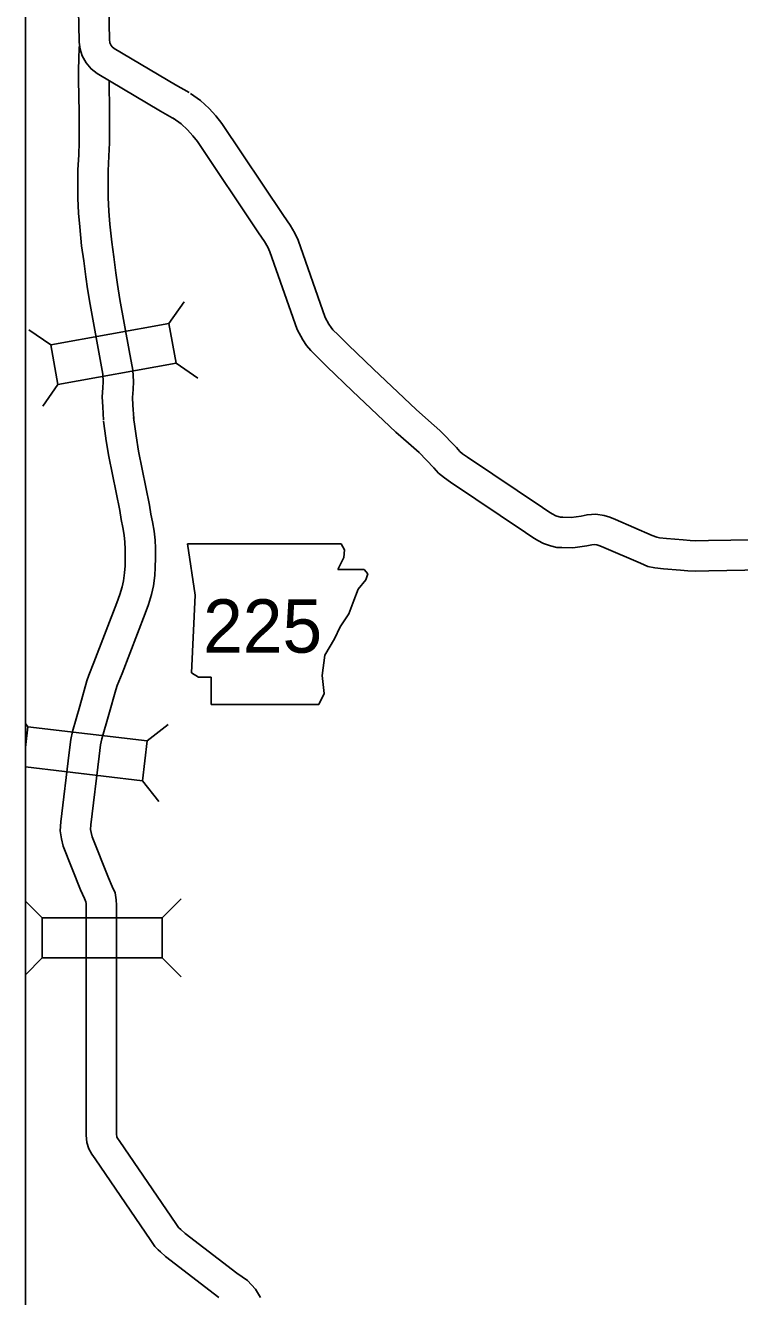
# Model space of a CAD drawing. Extents: x 1212896 to 1368412, y 378476 to 478763.
# Drawn here: x 1215273 to 1222342, y 456675 to 469257 of the extents above; entities that cross this region are included whole.
import ezdxf

# ---------------------------------------------------------------- set-up
doc = ezdxf.new("R2010")
doc.units = 0
for name, color, linetype in [('1', 7, 'Continuous'), ('Level 10', 7, 'Continuous'), ('Level 20', 7, 'Continuous'), ('Level 21', 7, 'Continuous')]:
    doc.layers.add(name, color=color, linetype=linetype)

msp = doc.modelspace()

# ---------------------------------------------------------------- linework, layer by layer
at = {"layer": '1'}
msp.add_lwpolyline([(1215273, 477661), (1246287, 477661), (1246287, 445613), (1215273, 445613)], close=True, dxfattribs=at)
at = {"layer": 'Level 10'}
for points in [[(1216748, 468330), (1216609, 468408), (1215985, 468779), (1215924, 468826), (1215873, 468887), (1215836, 468954), (1215816, 469022), (1215806, 469092), (1215802, 469266), (1215802, 469318), (1215794, 469358), (1215783, 469400), (1215756, 469454), (1215592, 469769), (1215561, 469840), (1215534, 469911), (1215508, 470003), (1215498, 470075), (1215382, 470508), (1215369, 470572), (1215364, 470657), (1215364, 470750), (1215365, 470899)], [(1216895, 468591), (1216759, 468667), (1216153, 469028), (1216133, 469044), (1216122, 469057), (1216115, 469070), (1216110, 469085), (1216106, 469117), (1216102, 469271), (1216101, 469348), (1216086, 469426), (1216065, 469505), (1216024, 469589), (1215863, 469898), (1215839, 469954), (1215819, 470005), (1215803, 470064), (1215793, 470134), (1215674, 470578), (1215667, 470611), (1215664, 470665), (1215664, 470749), (1215665, 470896)], [(1216045, 465351), (1216038, 465481), (1216033, 465579), (1216041, 465671), (1216044, 465728), (1216039, 465805), (1216005, 465986), (1215913, 466494), (1215888, 466649), (1215872, 466769), (1215851, 466926), (1215829, 467074), (1215811, 467263), (1215800, 467397), (1215791, 467546), (1215791, 467696), (1215793, 467828), (1215801, 467975), (1215806, 468102), (1215806, 468268), (1215804, 468393), (1215800, 468718), (1215800, 468826), (1215801, 468917), (1215804, 469047)], [(1216345, 465367), (1216338, 465497), (1216334, 465574), (1216340, 465652), (1216344, 465731), (1216337, 465843), (1216300, 466040), (1216209, 466544), (1216185, 466693), (1216169, 466808), (1216148, 466967), (1216127, 467110), (1216110, 467290), (1216099, 467419), (1216091, 467554), (1216091, 467693), (1216093, 467818), (1216100, 467961), (1216106, 468095), (1216106, 468270), (1216104, 468397), (1216101, 468707)], [(1222923, 464173), (1222034, 464157), (1221910, 464155), (1221852, 464157), (1221783, 464164), (1221617, 464177), (1221550, 464185), (1221523, 464190), (1221477, 464209), (1221114, 464366), (1221059, 464388), (1221000, 464407), (1220918, 464420), (1220832, 464414), (1220775, 464400), (1220674, 464387), (1220592, 464389), (1220568, 464389), (1220555, 464392), (1220523, 464404), (1220488, 464422), (1220453, 464442), (1220390, 464485), (1219648, 464984), (1219601, 465017), (1219574, 465039), (1219540, 465080), (1219376, 465246), (1219264, 465347), (1219140, 465454), (1218718, 465854), (1218467, 466095), (1218368, 466194), (1218316, 466244), (1218298, 466265), (1218277, 466298), (1218239, 466367), (1217972, 467130), (1217940, 467200), (1217895, 467280), (1217829, 467374), (1217217, 468287), (1217158, 468360), (1217091, 468434), (1217006, 468515), (1216907, 468584)], [(1222929, 463873), (1222039, 463857), (1221907, 463855), (1221831, 463858), (1221756, 463866), (1221589, 463879), (1221503, 463888), (1221435, 463902), (1221360, 463933), (1220999, 464089), (1220959, 464105), (1220930, 464114), (1220905, 464118), (1220880, 464116), (1220829, 464104), (1220690, 464087), (1220584, 464089), (1220532, 464090), (1220470, 464104), (1220402, 464129), (1220344, 464159), (1220295, 464187), (1220223, 464236), (1219479, 464736), (1219420, 464777), (1219362, 464825), (1219317, 464878), (1219169, 465029), (1219066, 465122), (1218939, 465231), (1218511, 465637), (1218257, 465881), (1218158, 465980), (1218098, 466038), (1218056, 466087), (1218019, 466145), (1217964, 466246), (1217694, 467017), (1217673, 467063), (1217641, 467119), (1217581, 467204), (1216976, 468108), (1216930, 468165), (1216876, 468224), (1216816, 468282), (1216736, 468337)], [(1217189, 456664), (1216659, 457071), (1216610, 457116), (1216586, 457137), (1216553, 457172), (1216514, 457231), (1215962, 458039), (1215931, 458083), (1215900, 458138), (1215882, 458200), (1215876, 458274), (1215874, 460218), (1215875, 460543), (1215874, 460566), (1215871, 460581), (1215857, 460615), (1215818, 460702), (1215648, 461134), (1215630, 461206), (1215616, 461285), (1215623, 461373), (1215705, 462061), (1215723, 462187), (1215740, 462267), (1215811, 462518), (1215881, 462769), (1215901, 462826), (1215951, 462952), (1216177, 463542), (1216208, 463624), (1216232, 463701), (1216245, 463759), (1216254, 463838), (1216259, 463906), (1216261, 463989), (1216260, 464074), (1216257, 464141), (1216251, 464211), (1216236, 464286), (1216221, 464367), (1216207, 464454), (1216099, 464991), (1216073, 465145), (1216058, 465245), (1216046, 465341)], [(1217601, 456665), (1217549, 456749), (1217470, 456833), (1217367, 456906), (1216853, 457300), (1216810, 457340), (1216793, 457354), (1216788, 457360), (1216762, 457398), (1216209, 458210), (1216185, 458243), (1216179, 458254), (1216176, 458286), (1216174, 460218), (1216176, 460550), (1216173, 460603), (1216160, 460670), (1216132, 460735), (1216095, 460818), (1215934, 461226), (1215924, 461268), (1215918, 461299), (1215922, 461343), (1216003, 462023), (1216018, 462135), (1216031, 462194), (1216100, 462437), (1216168, 462680), (1216182, 462722), (1216230, 462843), (1216458, 463435), (1216492, 463526), (1216522, 463623), (1216542, 463710), (1216553, 463811), (1216558, 463890), (1216561, 463986), (1216560, 464083), (1216556, 464162), (1216548, 464252), (1216531, 464342), (1216516, 464419), (1216502, 464508), (1216394, 465044), (1216370, 465193), (1216355, 465287), (1216344, 465377)]]:
    msp.add_lwpolyline(points, dxfattribs=at)
at = {"layer": 'Level 20'}
for p, q in [((1216694, 466305), (1216844, 466522)), ((1216694, 466305), (1215525, 466094)), ((1216764, 465915), (1216694, 466305)), ((1215525, 466094), (1215308, 466245)), ((1215525, 466094), (1215595, 465704)), ((1215595, 465704), (1216764, 465915)), ((1216764, 465915), (1216981, 465765)), ((1215595, 465704), (1215444, 465487)), ((1215298, 462315), (1215273, 462346)), ((1215298, 462315), (1215273, 462110)), ((1216477, 462175), (1215298, 462315)), ((1216477, 462175), (1216685, 462338)), ((1216431, 461781), (1216477, 462175)), ((1215273, 461919), (1216431, 461781)), ((1216431, 461781), (1216594, 461574)), ((1215439, 460422), (1215273, 460588)), ((1216627, 460423), (1216814, 460610)), ((1216627, 460423), (1215439, 460422)), ((1215439, 460422), (1215440, 460026)), ((1216628, 460027), (1216627, 460423)), ((1215440, 460026), (1215273, 459859)), ((1215440, 460026), (1216628, 460027)), ((1216628, 460027), (1216815, 459841))]:
    msp.add_line(p, q, dxfattribs=at)
at = {"layer": 'Level 21'}
for p, q in [((1216952, 463617), (1216876, 464124)), ((1216876, 464124), (1218397, 464124)), ((1218397, 464124), (1218432, 464065)), ((1218398, 464124), (1218398, 464124)), ((1218432, 464065), (1218424, 463989)), ((1218424, 463989), (1218365, 463871)), ((1218365, 463871), (1218627, 463871)), ((1218644, 463769), (1218568, 463676)), ((1218627, 463871), (1218661, 463828)), ((1218661, 463828), (1218644, 463769)), ((1218525, 463566), (1218568, 463676)), ((1216918, 462847), (1216952, 463617)), ((1218525, 463566), (1218475, 463431)), ((1218475, 463431), (1218390, 463304)), ((1218390, 463304), (1218331, 463186)), ((1218331, 463186), (1218238, 463025)), ((1218238, 463025), (1218212, 462822)), ((1216986, 462805), (1216918, 462847)), ((1217113, 462805), (1216986, 462805)), ((1217113, 462534), (1217113, 462805)), ((1218212, 462822), (1218229, 462644)), ((1218229, 462644), (1218179, 462534)), ((1218179, 462534), (1217113, 462534))]:
    msp.add_line(p, q, dxfattribs=at)

# ---------------------------------------------------------------- texts
msp.add_text('225', height=528, dxfattribs=at).set_placement((1217032, 463048))

doc.saveas('drawing.dxf')
